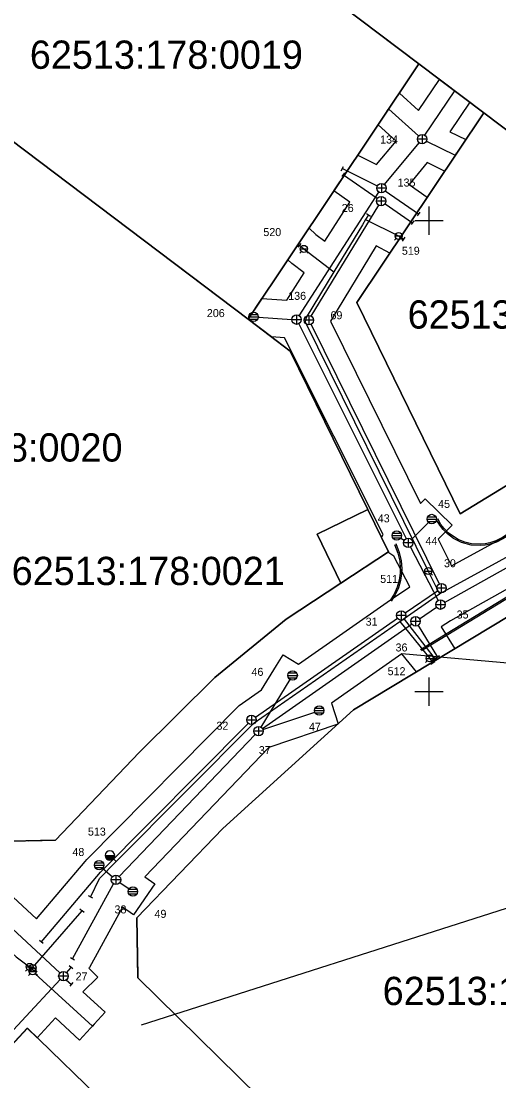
# Model space of a CAD drawing. Extents: x 531722 to 532110, y 6469397 to 6469678.
# Drawn here: x 531856.7 to 531907.4, y 6469508.7 to 6469621.2 of the extents above; entities that cross this region are included whole.
import ezdxf

# ---------------------------------------------------------------- set-up
doc = ezdxf.new("R2010")
doc.units = 0
for name, color, linetype in [('ABIJOONIS', 7, 'Continuous'), ('Default', 7, 'Continuous'), ('IKÕ alad', 7, 'Continuous'), ('KAEVUNR_KKAEV', 7, 'Continuous'), ('KAEVUNR_SKKAEV', 7, 'Continuous'), ('KAEVUNR_VKAEV', 7, 'Continuous'), ('KKAEV', 7, 'Continuous'), ('KTRASS', 7, 'Continuous'), ('PIIR', 7, 'Continuous'), ('PIIRIMLEITUD', 7, 'Continuous'), ('SKKAEV', 7, 'Continuous'), ('SKTRASS', 7, 'Continuous'), ('TEE', 7, 'Continuous'), ('VKAEV', 7, 'Continuous'), ('VORK', 7, 'Continuous'), ('VTRASS', 7, 'Continuous')]:
    doc.layers.add(name, color=color, linetype=linetype)

msp = doc.modelspace()

# ---------------------------------------------------------------- linework, layer by layer
at = {"layer": 'Default'}
for q in [(531897.12, 6469554), (531869.45, 6469514.57)]:
    msp.add_line((531972.02, 6469547.42), q, dxfattribs=at)
at = {"layer": 'IKÕ alad'}
for points in [[(531858.3, 6469525.87), (531863.47, 6469531.96), (531863.65, 6469532.17), (531879.85, 6469548.51), (531882.22, 6469550.17), (531883.81, 6469552.77), (531884.5, 6469553.9), (531886.13, 6469552.9), (531895.93, 6469559.74), (531897.97, 6469561.13), (531896.28, 6469564.39), (531895.63, 6469564.8), (531895.7, 6469564.85), (531894.96, 6469566.37), (531895.12, 6469566.67), (531884.66, 6469587.57), (531883.28, 6469587.65), (531880.79, 6469589.54), (531882.26, 6469591.73), (531884.89, 6469591.56), (531886.76, 6469594.45), (531885.43, 6469595.46), (531885.01, 6469595.85), (531887.26, 6469599.21), (531888, 6469598.53), (531888.93, 6469597.82), (531891.6, 6469601.96), (531889.9, 6469603.15), (531892.44, 6469606.94), (531894.43, 6469605.95), (531896.51, 6469608.45), (531894.6, 6469610.17), (531896.86, 6469613.55), (531898.9, 6469611.68), (531901.13, 6469614.98), (531904.33, 6469612.57), (531902.22, 6469609.44), (531903.91, 6469608.61), (531901.66, 6469605.26), (531899.81, 6469606.17), (531897.88, 6469603.85), (531899.81, 6469602.49), (531895.84, 6469596.56), (531894.38, 6469597.33), (531889.53, 6469589.34), (531899.1, 6469569.97), (531899.6, 6469570.47), (531902.46, 6469567.67), (531900.98, 6469566.17), (531902.38, 6469563.34), (531909.07, 6469567.01)], [(531910.44, 6469562.09), (531902.27, 6469557.52), (531901.29, 6469556.87), (531902.73, 6469554.54), (531898.67, 6469552.09), (531897.12, 6469554), (531889.63, 6469548.76), (531890.37, 6469546.59), (531890.31, 6469546.54), (531883, 6469544.06), (531869.82, 6469530.33), (531870.9, 6469529.59), (531868.62, 6469526.3), (531867.44, 6469527.11), (531863.93, 6469520.72), (531863.88, 6469520.62)], [(531833.41, 6469548.99), (531858.3, 6469525.87)], [(531863.88, 6469520.62), (531864.82, 6469519.68), (531863.25, 6469518.11), (531865.6, 6469515.95), (531862.9, 6469513), (531860.34, 6469515.35), (531858.38, 6469513.23), (531857.33, 6469514.25), (531825.63, 6469480.06)]]:
    msp.add_lwpolyline(points, dxfattribs=at)
at = {"layer": 'KKAEV'}
for p, q in [((531895.42, 6469602.07), (531894.42, 6469602.07)), ((531894.92, 6469602.58), (531894.92, 6469601.58)), ((531887.24, 6469589.93), (531887.24, 6469588.93)), ((531887.75, 6469589.43), (531886.75, 6469589.43)), ((531901.82, 6469560.98), (531900.82, 6469560.98)), ((531901.31, 6469561.49), (531901.31, 6469560.49)), ((531897.05, 6469558.59), (531897.05, 6469557.59)), ((531897.55, 6469558.08), (531896.55, 6469558.08)), ((531881.65, 6469546.98), (531880.65, 6469546.98)), ((531881.14, 6469547.49), (531881.14, 6469546.49))]:
    msp.add_line(p, q, dxfattribs=at)
for centre in [(531894.92, 6469602.08), (531887.25, 6469589.43), (531901.32, 6469560.99), (531897.05, 6469558.09), (531881.15, 6469546.99)]:
    msp.add_circle(centre, 0.5, dxfattribs=at)
at = {"layer": 'KTRASS'}
for p, q in [((531890.79, 6469604.67), (531891.07, 6469605.08)), ((531898.39, 6469599.99), (531898.1, 6469599.58)), ((531900.87, 6469553.61), (531900.47, 6469553.3)), ((531859.03, 6469523.27), (531858.65, 6469523.59))]:
    msp.add_line(p, q, dxfattribs=at)
for points in [[(531890.93, 6469604.87), (531894.51, 6469602.37)], [(531887.5, 6469589.86), (531894.66, 6469601.65)], [(531895.33, 6469601.8), (531898.24, 6469599.78)], [(531887.47, 6469588.99), (531901.09, 6469561.43)], [(531897.46, 6469558.37), (531900.9, 6469560.7)], [(531881.56, 6469547.27), (531896.64, 6469557.81)], [(531897.36, 6469557.7), (531900.67, 6469553.45)], [(531858.84, 6469523.43), (531865.12, 6469530.82), (531880.79, 6469546.63)]]:
    msp.add_lwpolyline(points, dxfattribs=at)
at = {"layer": 'PIIR'}
for points in [[(531894.32, 6469620.12), (531898.93, 6469616.64), (531880.79, 6469589.54), (531873.25, 6469595.23)], [(531956.63, 6469617.16), (531957.93, 6469615.9), (531933.2, 6469590.77), (531905.81, 6469611.45), (531898.93, 6469616.64), (531894.32, 6469620.12)], [(531857.49, 6469534.17), (531860.32, 6469534.24), (531869.22, 6469543.55), (531877.27, 6469551.51), (531884.83, 6469557.69), (531890.65, 6469561.52), (531895.7, 6469564.85), (531893.5, 6469569.34), (531885.26, 6469586.16), (531880.79, 6469589.54), (531898.93, 6469616.64), (531905.81, 6469611.45), (531892.32, 6469591.31), (531903.32, 6469568.86), (531920.82, 6469579.55)], [(531873.25, 6469595.23), (531880.79, 6469589.54), (531885.26, 6469586.16), (531893.5, 6469569.34), (531888.12, 6469566.7), (531890.65, 6469561.52), (531884.83, 6469557.69), (531877.27, 6469551.51), (531869.22, 6469543.55), (531860.32, 6469534.24), (531857.49, 6469534.17)], [(531869.08, 6469519.75), (531868.96, 6469525.97), (531878.09, 6469535.46), (531892, 6469548.07), (531908.6, 6469558.08), (531911.02, 6469553.14)], [(531908.6, 6469558.08), (531892, 6469548.07), (531878.09, 6469535.46), (531868.96, 6469525.97), (531869.08, 6469519.75)]]:
    msp.add_lwpolyline(points, dxfattribs=at)
for points in [[(531905.81, 6469611.45), (531933.2, 6469590.77), (531920.82, 6469579.55), (531903.32, 6469568.86), (531892.32, 6469591.31)], [(531893.5, 6469569.34), (531895.7, 6469564.85), (531890.65, 6469561.52), (531888.12, 6469566.7)]]:
    msp.add_lwpolyline(points, close=True, dxfattribs=at)
at = {"layer": 'PIIRIMLEITUD'}
for points in [[(531899.65, 6469672.42), (531957.93, 6469615.9), (531933.2, 6469590.77), (531905.81, 6469611.45), (531898.93, 6469616.64), (531861.91, 6469644.6), (531880.45, 6469659.84)], [(531861.91, 6469644.6), (531898.93, 6469616.64), (531880.79, 6469589.54), (531839.63, 6469620.61)], [(531839.63, 6469620.61), (531880.79, 6469589.54), (531885.26, 6469586.16), (531893.5, 6469569.34), (531888.12, 6469566.7), (531890.65, 6469561.52), (531884.83, 6469557.69), (531877.27, 6469551.51), (531869.22, 6469543.55), (531860.32, 6469534.24), (531853.97, 6469534.09), (531836.09, 6469550.67), (531814.22, 6469570.39), (531816.81, 6469573.34), (531806.3, 6469582.57), (531811.61, 6469585.84), (531822.45, 6469596.58)], [(531905.81, 6469611.45), (531933.2, 6469590.77), (531920.82, 6469579.55), (531903.32, 6469568.86), (531892.32, 6469591.31)], [(531893.5, 6469569.34), (531895.7, 6469564.85), (531890.65, 6469561.52), (531888.12, 6469566.7)], [(531857.35, 6469514.26), (531865.97, 6469505.91), (531834.75, 6469472.24), (531825.66, 6469480.07)]]:
    msp.add_lwpolyline(points, close=True, dxfattribs=at)
for points in [[(531853.97, 6469534.09), (531860.32, 6469534.24), (531869.22, 6469543.55), (531877.27, 6469551.51), (531884.83, 6469557.69), (531890.65, 6469561.52), (531895.7, 6469564.85), (531893.5, 6469569.34), (531885.26, 6469586.16), (531880.79, 6469589.54), (531898.93, 6469616.64), (531905.81, 6469611.45), (531892.32, 6469591.31), (531903.32, 6469568.86), (531920.82, 6469579.55)], [(531908.6, 6469558.08), (531892, 6469548.07), (531878.09, 6469535.46), (531868.96, 6469525.97), (531869.08, 6469519.62), (531890.48, 6469498.54)], [(531927.55, 6469493.15), (531911.54, 6469477.11), (531890.48, 6469498.54), (531869.08, 6469519.62), (531868.96, 6469525.97), (531878.09, 6469535.46), (531892, 6469548.07), (531908.6, 6469558.08), (531913.6, 6469547.88), (531950.63, 6469516.26), (531944.16, 6469509.78)], [(531865.97, 6469505.91), (531857.35, 6469514.26), (531825.66, 6469480.07)]]:
    msp.add_lwpolyline(points, dxfattribs=at)
at = {"layer": 'SKKAEV'}
for p, q in [((531899.27, 6469609.16), (531899.27, 6469608.16)), ((531899.77, 6469608.65), (531898.77, 6469608.65)), ((531895.45, 6469603.45), (531894.45, 6469603.45)), ((531894.95, 6469603.96), (531894.95, 6469602.96)), ((531880.88, 6469589.78), (531881.88, 6469589.78)), ((531880.95, 6469590.03), (531881.82, 6469590.03)), ((531885.93, 6469589.99), (531885.93, 6469588.99)), ((531880.95, 6469589.53), (531881.82, 6469589.53)), ((531886.44, 6469589.48), (531885.44, 6469589.48)), ((531899.8, 6469568.32), (531900.8, 6469568.32)), ((531899.86, 6469568.57), (531900.73, 6469568.57)), ((531899.86, 6469568.07), (531900.73, 6469568.07)), ((531896.08, 6469566.56), (531897.08, 6469566.56)), ((531896.15, 6469566.81), (531897.02, 6469566.81)), ((531896.15, 6469566.31), (531897.02, 6469566.31)), ((531897.8, 6469566.29), (531897.8, 6469565.29)), ((531898.3, 6469565.78), (531897.3, 6469565.78)), ((531901.22, 6469559.73), (531901.22, 6469558.73)), ((531901.72, 6469559.22), (531900.72, 6469559.22)), ((531899.07, 6469557.45), (531898.07, 6469557.45)), ((531898.57, 6469557.96), (531898.57, 6469556.96)), ((531885.02, 6469551.72), (531886.02, 6469551.72)), ((531885.08, 6469551.98), (531885.95, 6469551.98)), ((531885.08, 6469551.47), (531885.95, 6469551.47)), ((531887.92, 6469548.24), (531888.78, 6469548.24)), ((531887.85, 6469547.99), (531888.85, 6469547.99)), ((531887.92, 6469547.74), (531888.78, 6469547.74)), ((531881.9, 6469546.31), (531881.9, 6469545.31)), ((531882.4, 6469545.8), (531881.4, 6469545.8)), ((531864.46, 6469531.58), (531865.46, 6469531.58)), ((531864.53, 6469531.83), (531865.39, 6469531.83)), ((531864.53, 6469531.33), (531865.39, 6469531.33)), ((531866.76, 6469530.52), (531866.76, 6469529.52)), ((531867.26, 6469530.02), (531866.26, 6469530.02)), ((531868.12, 6469529.02), (531868.99, 6469529.02)), ((531868.06, 6469528.77), (531869.06, 6469528.77)), ((531868.12, 6469528.52), (531868.99, 6469528.52)), ((531861.16, 6469520.29), (531861.16, 6469519.29)), ((531861.67, 6469519.79), (531860.67, 6469519.79))]:
    msp.add_line(p, q, dxfattribs=at)
for centre in [(531899.27, 6469608.66), (531894.95, 6469603.46), (531881.38, 6469589.78), (531885.94, 6469589.49), (531900.3, 6469568.32), (531896.58, 6469566.56), (531897.8, 6469565.79), (531901.22, 6469559.23), (531898.57, 6469557.46), (531885.52, 6469551.72), (531888.35, 6469547.99), (531881.9, 6469545.81), (531864.96, 6469531.58), (531866.76, 6469530.02), (531868.56, 6469528.77), (531861.17, 6469519.79)]:
    msp.add_circle(centre, 0.5, dxfattribs=at)
at = {"layer": 'SKTRASS'}
for p, q in [((531902.52, 6469613.91), (531902.94, 6469613.63)), ((531895.56, 6469611.67), (531895.89, 6469612.04)), ((531902.9, 6469607.16), (531902.68, 6469606.71)), ((531890.69, 6469605.3), (531890.91, 6469605.75)), ((531899.02, 6469600.91), (531898.73, 6469600.5)), ((531901.13, 6469553.8), (531900.71, 6469553.54)), ((531862.36, 6469521.5), (531861.92, 6469521.75)), ((531861.52, 6469520.14), (531862, 6469520.72)), ((531862.19, 6469520.56), (531861.8, 6469520.88)), ((531861.47, 6469519.4), (531862.05, 6469518.92)), ((531861.89, 6469518.73), (531862.21, 6469519.12))]:
    msp.add_line(p, q, dxfattribs=at)
for points in [[(531899.55, 6469609.07), (531902.73, 6469613.77)], [(531895.73, 6469611.85), (531898.9, 6469608.99)], [(531895.27, 6469603.85), (531898.95, 6469608.27)], [(531899.72, 6469608.44), (531902.79, 6469606.94)], [(531890.8, 6469605.52), (531894.5, 6469603.68)], [(531886.21, 6469589.91), (531894.68, 6469603.04)], [(531895.36, 6469603.17), (531898.88, 6469600.71)], [(531881.88, 6469589.75), (531885.44, 6469589.52)], [(531886.16, 6469589.04), (531897.58, 6469566.24)], [(531898.15, 6469566.15), (531899.94, 6469567.97)], [(531897.01, 6469566.3), (531897.38, 6469566.06)], [(531898.04, 6469565.35), (531900.99, 6469559.67)], [(531901.66, 6469559.47), (531910.58, 6469564.46)], [(531898.99, 6469557.74), (531900.81, 6469558.95)], [(531882.31, 6469546.09), (531898.16, 6469557.17)], [(531898.84, 6469557.03), (531900.92, 6469553.67)], [(531882.16, 6469546.23), (531885.26, 6469551.3)], [(531882.37, 6469545.97), (531887.88, 6469547.83)], [(531832.06, 6469546.82), (531860.8, 6469520.13)], [(531867.1, 6469530.38), (531881.55, 6469545.45)], [(531865.34, 6469531.25), (531866.38, 6469530.35)], [(531862.14, 6469521.62), (531866.51, 6469529.59)], [(531867.17, 6469529.74), (531868.15, 6469529.06)], [(531837.8, 6469494.77), (531849.68, 6469507.5), (531852.65, 6469510.67), (531860.82, 6469519.43)]]:
    msp.add_lwpolyline(points, dxfattribs=at)
at = {"layer": 'TEE'}
for points in [[(531909.08, 6469567.14), (531908.81, 6469566.98), (531907.79, 6469566.36), (531907.11, 6469566.01), (531906.46, 6469565.8), (531905.95, 6469565.7), (531905.43, 6469565.65), (531904.51, 6469565.7), (531903.79, 6469565.87), (531903.51, 6469565.97), (531903.1, 6469566.15), (531902.7, 6469566.38), (531902.05, 6469566.86), (531901.6, 6469567.31), (531901.26, 6469567.75), (531900.93, 6469568.33)], [(531909.18, 6469567.03), (531908.91, 6469566.86), (531907.86, 6469566.23), (531907.17, 6469565.87), (531906.5, 6469565.65), (531905.97, 6469565.55), (531905.43, 6469565.5), (531904.49, 6469565.56), (531903.46, 6469565.83), (531902.62, 6469566.25), (531901.95, 6469566.74), (531901.49, 6469567.21), (531901.14, 6469567.67), (531900.8, 6469568.25)], [(531896.34, 6469565.63), (531896.7, 6469564.71), (531896.89, 6469563.85), (531896.95, 6469563.06), (531896.93, 6469562.56), (531896.83, 6469561.83), (531896.62, 6469561.08), (531896.29, 6469560.33), (531895.92, 6469559.73)], [(531896.47, 6469565.71), (531896.85, 6469564.75), (531897.04, 6469563.87), (531897.1, 6469563.06), (531897.08, 6469562.55), (531896.97, 6469561.8), (531896.76, 6469561.03), (531896.42, 6469560.26), (531896, 6469559.59)], [(531912.82, 6469562.81), (531912.49, 6469562.61), (531907.91, 6469559.81), (531901.1, 6469555.66), (531899.11, 6469554.44)], [(531912.92, 6469562.7), (531912.59, 6469562.5), (531907.98, 6469559.68), (531901.18, 6469555.53), (531899.19, 6469554.31)]]:
    msp.add_lwpolyline(points, dxfattribs=at)
at = {"layer": 'VKAEV'}
for p, q in [((531896.51, 6469598.1), (531896.34, 6469597.92)), ((531896.4, 6469598.37), (531897.15, 6469598.37)), ((531897.04, 6469598.1), (531897.22, 6469597.92)), ((531886.45, 6469596.73), (531886.27, 6469596.56)), ((531886.34, 6469597), (531887.09, 6469597)), ((531886.98, 6469596.73), (531887.16, 6469596.56)), ((531899.55, 6469562.8), (531900.3, 6469562.8)), ((531899.66, 6469562.53), (531899.48, 6469562.36)), ((531900.19, 6469562.53), (531900.36, 6469562.36)), ((531899.81, 6469553.26), (531899.63, 6469553.08)), ((531899.7, 6469553.53), (531900.45, 6469553.53)), ((531900.34, 6469553.26), (531900.52, 6469553.08)), ((531865.62, 6469532.6), (531866.62, 6469532.6)), ((531857.33, 6469520.51), (531857.15, 6469520.32)), ((531857.21, 6469520.77), (531857.96, 6469520.77)), ((531857.65, 6469520.4), (531857.47, 6469520.21)), ((531857.66, 6469520.04), (531857.47, 6469519.85)), ((531857.53, 6469520.66), (531858.28, 6469520.66)), ((531857.54, 6469520.3), (531858.29, 6469520.3)), ((531857.87, 6469520.54), (531858.08, 6469520.38)), ((531858.19, 6469520.44), (531858.4, 6469520.27)), ((531858.2, 6469520.07), (531858.41, 6469519.91))]:
    msp.add_line(p, q, dxfattribs=at)
for centre in [(531896.78, 6469598.37), (531886.71, 6469597), (531899.92, 6469562.8), (531900.08, 6469553.53), (531857.59, 6469520.77), (531857.91, 6469520.66), (531857.91, 6469520.3)]:
    msp.add_circle(centre, 0.375, dxfattribs=at)
for radius, start, end in [(0.5, 359.9987, 179.9718), (0.5, 180, 0), (0.475, 180, 0), (0.45, 180, 0), (0.425, 180, 0), (0.4, 180, 0), (0.375, 180, 0), (0.35, 180, 0), (0.325, 180, 0), (0.3, 180, 0), (0.275, 180, 0), (0.25, 180, 0), (0.225, 180, 0), (0.2, 180, 0), (0.175, 180, 0), (0.15, 180, 0), (0.125, 180, 0), (0.1, 180, 0), (0.075, 180, 0), (0.05, 180, 0), (0.025, 180, 0)]:
    msp.add_arc((531866.12, 6469532.6), radius, start, end, dxfattribs=at)
at = {"layer": 'VORK'}
for p, q in [((531900, 6469601.5), (531900, 6469598.5)), ((531898.5, 6469600), (531901.5, 6469600)), ((531900, 6469551.5), (531900, 6469548.5)), ((531898.5, 6469550), (531901.5, 6469550))]:
    msp.add_line(p, q, dxfattribs=at)
at = {"layer": 'VTRASS'}
for p, q in [((531893.36, 6469600.76), (531893.79, 6469600.49)), ((531886.1, 6469597.2), (531886.43, 6469597.58)), ((531897.42, 6469598.25), (531897.14, 6469597.83)), ((531900.62, 6469553.17), (531900.2, 6469552.89)), ((531864.29, 6469528.08), (531863.84, 6469528.3)), ((531862.92, 6469526.93), (531863.15, 6469526.73)), ((531863.38, 6469526.53), (531863.15, 6469526.73)), ((531864.05, 6469514.25), (531864.25, 6469514.47)), ((531864.45, 6469514.69), (531864.25, 6469514.47))]:
    msp.add_line(p, q, dxfattribs=at)
for points in [[(531864.06, 6469528.19), (531865, 6469530.17), (531866.78, 6469531.96), (531881.43, 6469546.7), (531896.89, 6469557.43), (531901.12, 6469560.37), (531910.44, 6469565.48), (531935.93, 6469584.36), (531949.85, 6469597.85), (531953.59, 6469601.48), (531958.66, 6469606.39), (531964.17, 6469612.12)], [(531893.58, 6469600.62), (531893.26, 6469600.12), (531892.93, 6469599.57), (531889.9, 6469594.58), (531886.95, 6469589.72), (531886.85, 6469589.24), (531899.92, 6469562.8), (531901.12, 6469560.37)], [(531893.26, 6469600.12), (531896.78, 6469598.37), (531897.28, 6469598.04)], [(531886.26, 6469597.39), (531886.71, 6469597), (531889.9, 6469594.58)], [(531782.14, 6469588.31), (531784.13, 6469586.62), (531789.32, 6469582.23), (531796.95, 6469575.76), (531805.76, 6469568.61), (531809.72, 6469565.4), (531816.57, 6469558.66), (531820.35, 6469555.2), (531823.08, 6469552.7), (531829.23, 6469546.44), (531832.59, 6469542.96), (531841.23, 6469535.35), (531844.37, 6469532.61), (531856.17, 6469521.83), (531857.59, 6469520.77)], [(531896.89, 6469557.43), (531900.08, 6469553.53), (531900.41, 6469553.03)], [(531866.78, 6469531.96), (531866.12, 6469532.6)], [(531858.15, 6469520.94), (531863.15, 6469526.73)], [(531858.19, 6469520.04), (531864.25, 6469514.47)]]:
    msp.add_lwpolyline(points, dxfattribs=at)

# ---------------------------------------------------------------- texts
at = {"layer": 'ABIJOONIS'}
for s, p in [('62513:178:0019', (531857.61, 6469616.12)), ('62513:178:0017', (531897.73, 6469588.54)), ('62513:178:0020', (531838.45, 6469574.42)), ('62513:178:0021', (531855.68, 6469561.31)), ('62513:178:0037', (531895.08, 6469516.72))]:
    msp.add_text(s, height=3, dxfattribs=at).set_placement(p)
at = {"layer": 'KAEVUNR_KKAEV'}
for s, p in [('26', (531890.74, 6469600.92)), ('69', (531889.54, 6469589.53)), ('30', (531901.59, 6469563.2)), ('31', (531893.27, 6469557)), ('32', (531877.43, 6469545.95))]:
    msp.add_text(s, height=0.85, dxfattribs=at).set_placement(p)
at = {"layer": 'KAEVUNR_SKKAEV'}
for s, p in [('134', (531894.81, 6469608.19)), ('135', (531896.67, 6469603.62)), ('136', (531885.05, 6469591.59)), ('206', (531876.41, 6469589.76)), ('45', (531900.97, 6469569.5)), ('43', (531894.56, 6469567.97)), ('44', (531899.63, 6469565.57)), ('35', (531902.94, 6469557.76)), ('36', (531896.45, 6469554.26)), ('46', (531881.15, 6469551.67)), ('47', (531887.25, 6469545.84)), ('37', (531881.93, 6469543.36)), ('48', (531862.13, 6469532.55)), ('38', (531866.6, 6469526.45)), ('49', (531870.85, 6469525.98)), ('27', (531862.47, 6469519.34))]:
    msp.add_text(s, height=0.85, dxfattribs=at).set_placement(p)
at = {"layer": 'KAEVUNR_VKAEV'}
for s, p in [('520', (531882.41, 6469598.36)), ('519', (531897.12, 6469596.38)), ('511', (531894.82, 6469561.54)), ('512', (531895.61, 6469551.74)), ('513', (531863.78, 6469534.71))]:
    msp.add_text(s, height=0.85, dxfattribs=at).set_placement(p)

doc.saveas('drawing.dxf')
